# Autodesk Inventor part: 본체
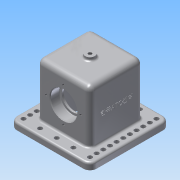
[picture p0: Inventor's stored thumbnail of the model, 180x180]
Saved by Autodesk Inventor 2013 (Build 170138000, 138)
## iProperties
Created: 2018-11
Part Number: 본체
Material: 알루미늄 6061
Document SubType Name: Modeling
Designer: Administrator
Density: 2.71 g/cm^3
Mass: 1020.43 g
Surface Area: 776.966 cm^2
Volume: 376.543 cm^3
Author: Administrator
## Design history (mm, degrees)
sketch "스케치1"
  geometry: L1 (-40, 40)-(40, 40); L2 (40, 40)-(40, -40); L3 (40, -40)-(-40, -40); L4 (-40, -40)-(-40, 40); L5 (-40, 40)-(40, -40); L6 (40, 40)-(-40, -40); 1 further point
  constraints: 12 end point, 2 midpoint, 2 parallel, 2 perpendicular, 1 horizontal
  dimensions: "d0" = 80 distance of L2.end L3.end
extrude "돌출1" new body sketch "스케치1" distance "d2" = 80; taper "d3" = 0 deg
sketch "스케치2"
  geometry: L1 (60, -60)-(-60, -60); L2 (-60, -60)-(-60, 60); L3 (-60, 60)-(60, 60); L4 (60, 60)-(60, -60); L5 (60, -60)-(-60, 60); L6 (-60, -60)-(60, 60); 1 further point
  constraints: 12 end point, 2 midpoint, 2 parallel, 2 perpendicular, 1 horizontal
  dimensions: "d4" = 120 distance of L2.end L3.end
extrude "돌출2" join sketch "스케치2" distance "d6" = 10; taper "d7" = 0 deg
sketch "스케치3"
  geometry: L1 (30, -23)-(-30, -23); L2 (-30, -23)-(-30, 23); L3 (-30, 23)-(30, 23); L4 (30, 23)-(30, -23); L5 (30, -23)-(-30, 23); L6 (-30, -23)-(30, 23); 1 further point
  constraints: 12 end point, 2 midpoint, 2 parallel, 1 horizontal, 1 perpendicular
  dimensions: "d8" = 46 distance of L3.end L1.start; "d10" = 60 distance of L2.end L3.end
extrude "돌출3" cut sketch "스케치3" distance "d11" = 80; taper "d12" = 0 deg
sketch "스케치4"
  geometry: L1 (100, -90)-(-20, -90) reference; 3 further points
  constraints: 1 midpoint, 1 vertical alignment
  dimensions: "d13" = 48 distance from line of point (40, -42) L1
hole "구멍1" sketch "스케치4" at (40, -42) diameter "d14" = 33; stored, may be unused: countersink angle "d18" = 90 deg, drill point angle "d20" = 118 deg; dims "d15" = 6, "d16" = 4, "d17" = 2, "d19" = 8
hole "구멍2" diameter "d23" = 40; stored, may be unused: countersink angle "d27" = 90 deg, drill point angle "d29" = 0 deg; dims "d21" = 10, "d22" = 10, "d24" = 6, "d25" = 4, "d26" = 2, "d28" = 14
sketch "스케치5"
  geometry: C1 r 7 at (0, 0); 1 further point
  constraints: 1 centre point, 1 coincident
  dimensions: "d30" = 14 diameter of C1
extrude "돌출4" join sketch "스케치5" distance "d32" = 5; taper "d33" = 0 deg
hole "구멍3" diameter "d36" = 4.917; stored, may be unused: countersink angle "d40" = 90 deg, drill point angle "d42" = 0 deg; dims "d34" = 10, "d35" = 10, "d37" = 6, "d38" = 4, "d39" = 2, "d41" = 14
fillet "모깎기1" dims "d43" = 10
fillet "모깎기2" dims "d44" = 8
fillet "모깎기3" dims "d45" = 8
sketch "스케치6"
  geometry: C1 r 20 at (32, 38) reference; 2 further points
  constraints: 1 vertical alignment
  dimensions: "d46" = 26 distance of point (32, 64) C1.centre
hole "구멍4" sketch "스케치6" at (32, 64) diameter "d47" = 3.242; stored, may be unused: countersink angle "d51" = 90 deg, drill point angle "d53" = 118 deg; dims "d48" = 8, "d49" = 4, "d50" = 2, "d52" = 10
chamfer "모따기1" distance "d57" = 1; stored, may be unused: second distance "d58" = 2, angle "d59" = 45 deg
fillet "모깎기4" dims "d60" = 3
fillet "모깎기5" dims "d61" = 3
fillet "모깎기6" dims "d62" = 0.6
sketch "스케치7"
  geometry: A1 r 7 centre (50, -50) between (50, -57) and (57, -50) reference; A2 r 7 centre (50, 50) between (57, 50) and (50, 57) reference; A3 r 7 centre (-50, 50) between (-50, 57) and (-57, 50) reference; A4 r 7 centre (-50, -50) between (-57, -50) and (-50, -57) reference; 29 further points
  constraints: 22 vertical alignment, 16 horizontal alignment, 4 coincident
  dimensions: "d63" = 25 distance of point (-25, -50) A4.centre; "d64" = 25 distance of point (0, -50) point (-25, -50); "d65" = 25 distance of point (25, -50) point (0, -50); "d66" = 25 distance of A1.centre point (25, -50) (derived); "d67" = 10 distance of point (-50, 40) point (-50, 50); "d68" = 10 distance of point (-50, 30) point (-50, 40); "d69" = 10 distance of point (-50, 20) point (-50, 30); "d70" = 10 distance of point (-50, 10) point (-50, 20); "d71" = 10 distance of point (-50, 0) point (-50, 10); "d72" = 10 distance of point (-50, -10) point (-50, 0); "d73" = 10 distance of point (-50, -20) point (-50, -10); "d74" = 10 distance of point (-50, -30) point (-50, -20); "d75" = 10 distance of point (-50, -40) point (-50, -30)
hole "구멍5" sketch "스케치7" diameter "d76" = 6.6; stored, may be unused: countersink angle "d80" = 90 deg, drill point angle "d82" = 118 deg; dims "d77" = 8, "d78" = 4, "d79" = 2, "d81" = 10
sketch "스케치8"
  geometry: L1 (82, -82)-(-18, -82) reference; 3 further points
  constraints: 1 midpoint, 1 vertical alignment, 1 other
  dimensions: "d83" = 48 distance from line of L1 point (32, -34)
feature "엠보싱1" sketch "스케치8" dims "d0" = 80, "d8" = 46, "d10" = 60, "d84" = 0.5, "d85" = 0
node "솔리드1"
mirror "대칭1"
pattern_circular "원형 패턴1" dims angle "d55" = 360 deg
mirror "대칭2"
